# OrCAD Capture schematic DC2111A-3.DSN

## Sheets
1 SHEET1: size Custom; title: HIGH EFFICIENCY 4 PHASE 120A; rev: 3; company: TM
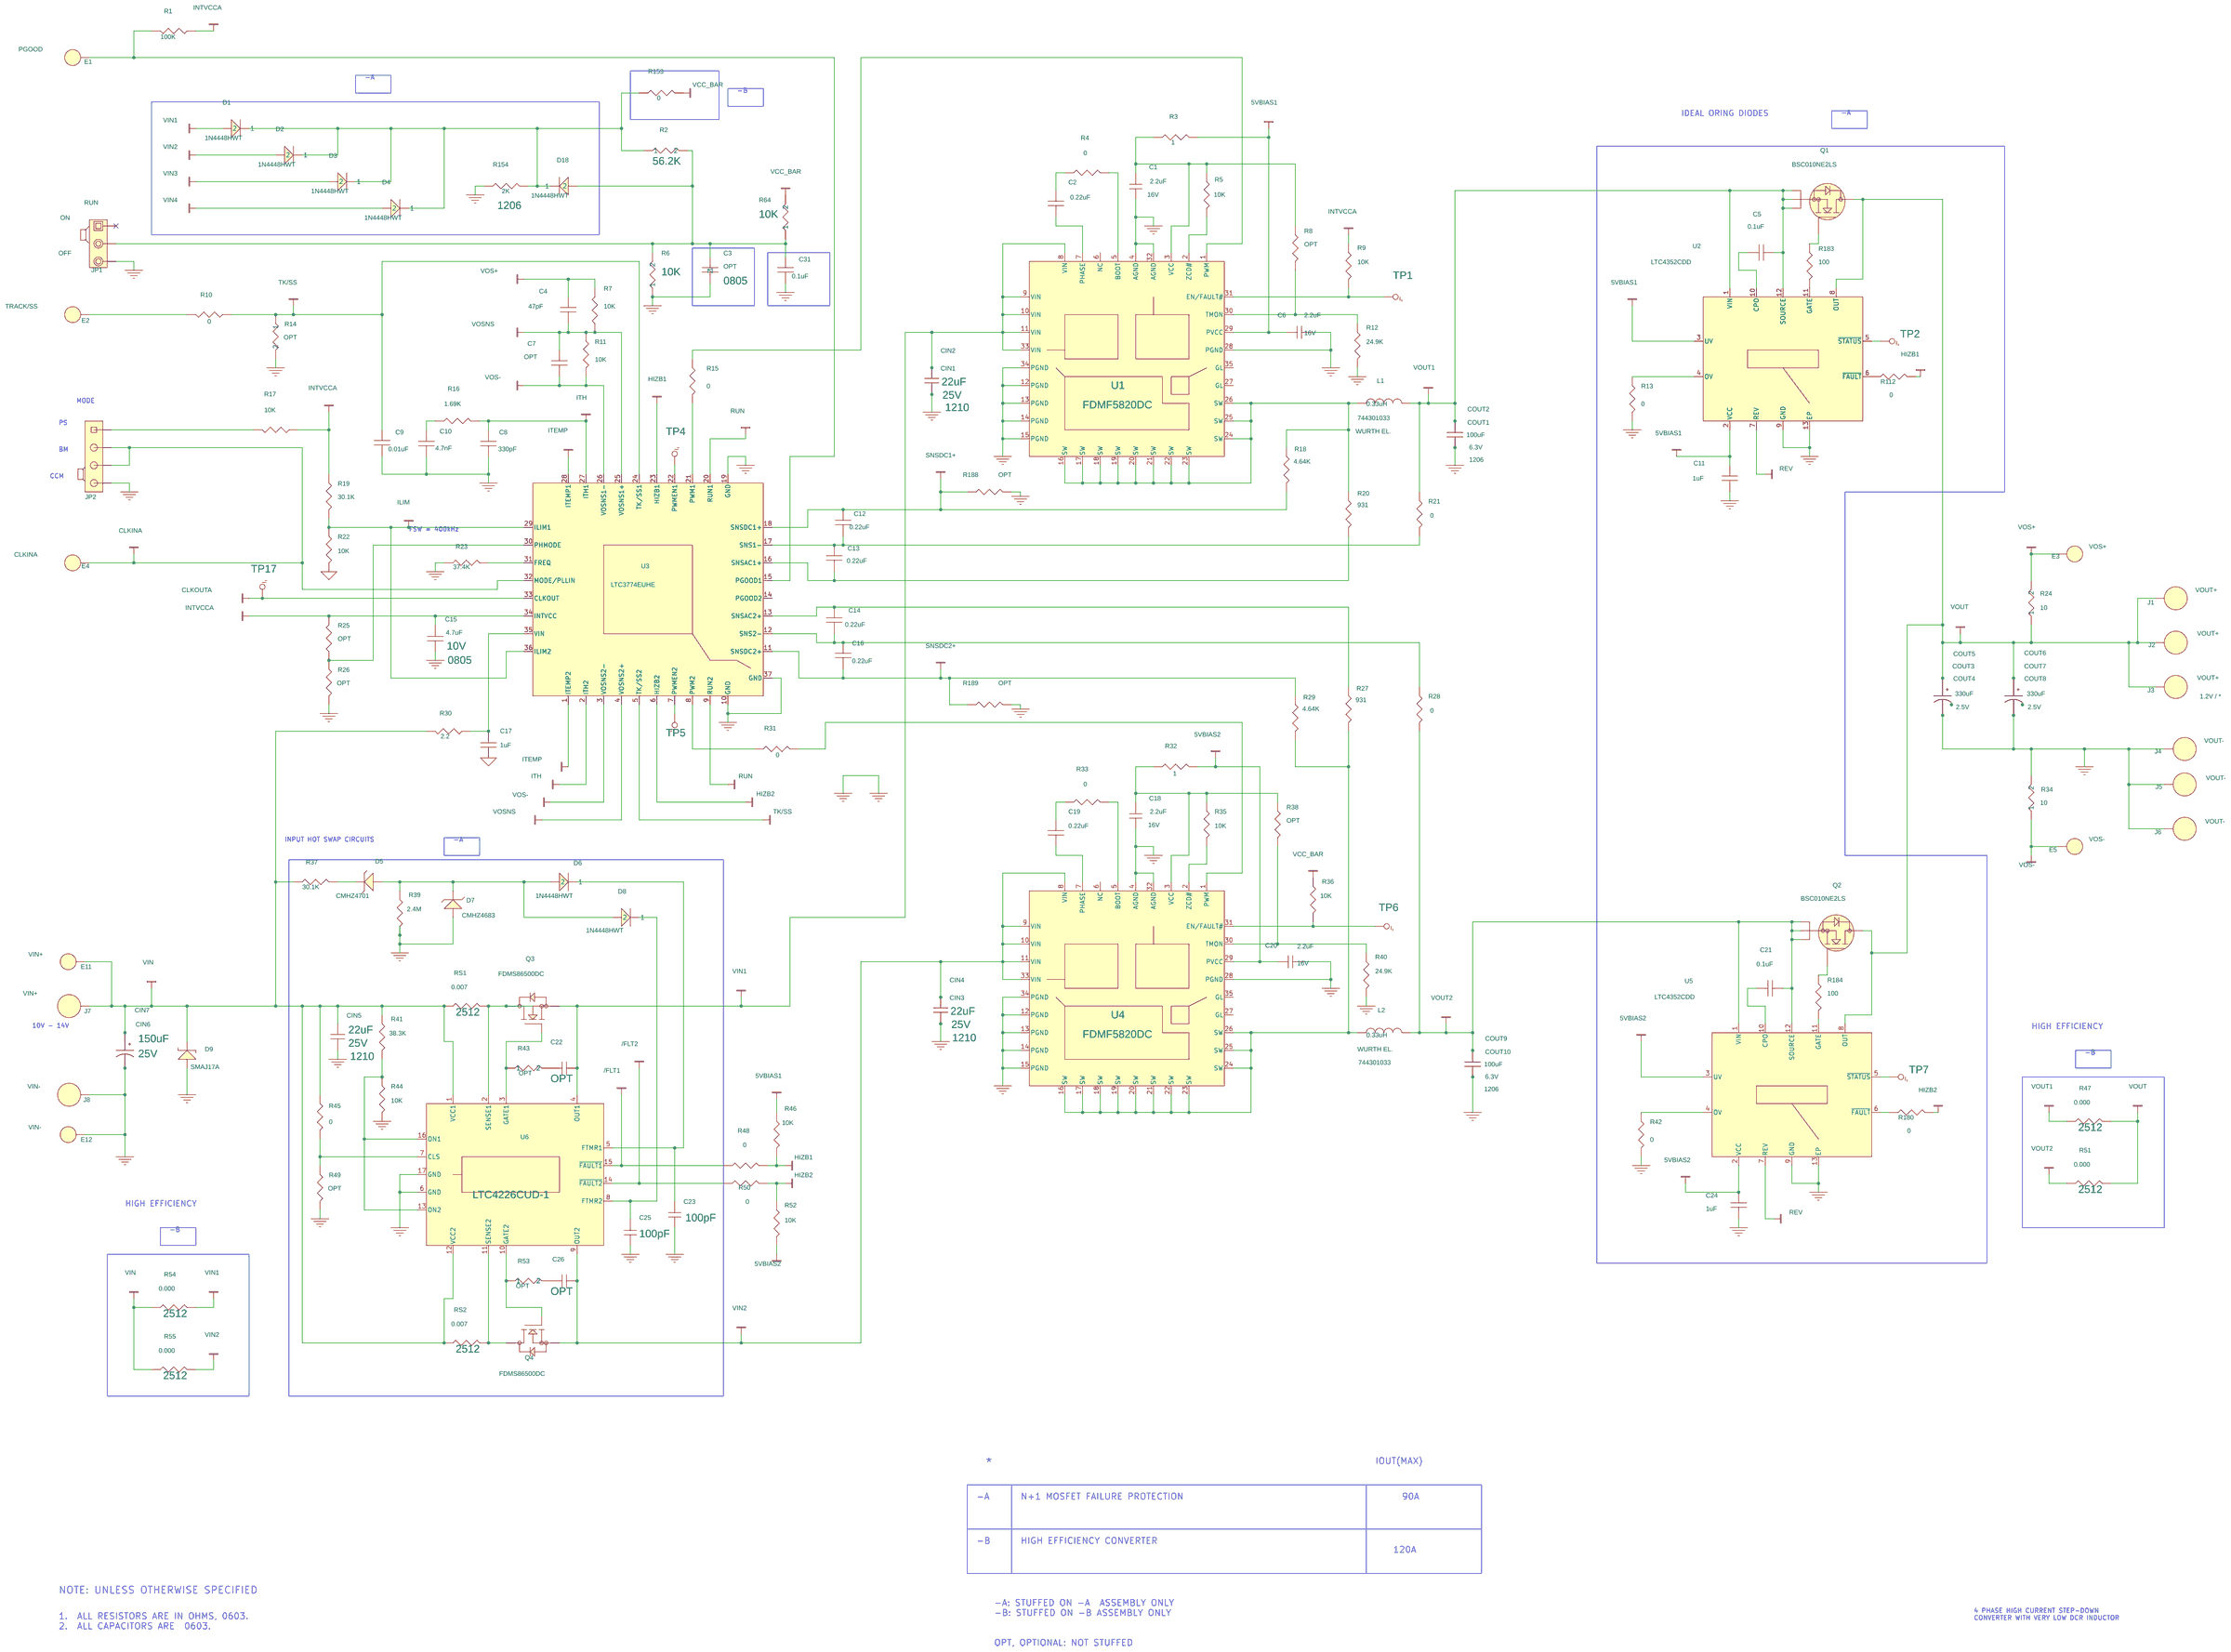
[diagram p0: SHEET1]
2 SHEET2: size Custom
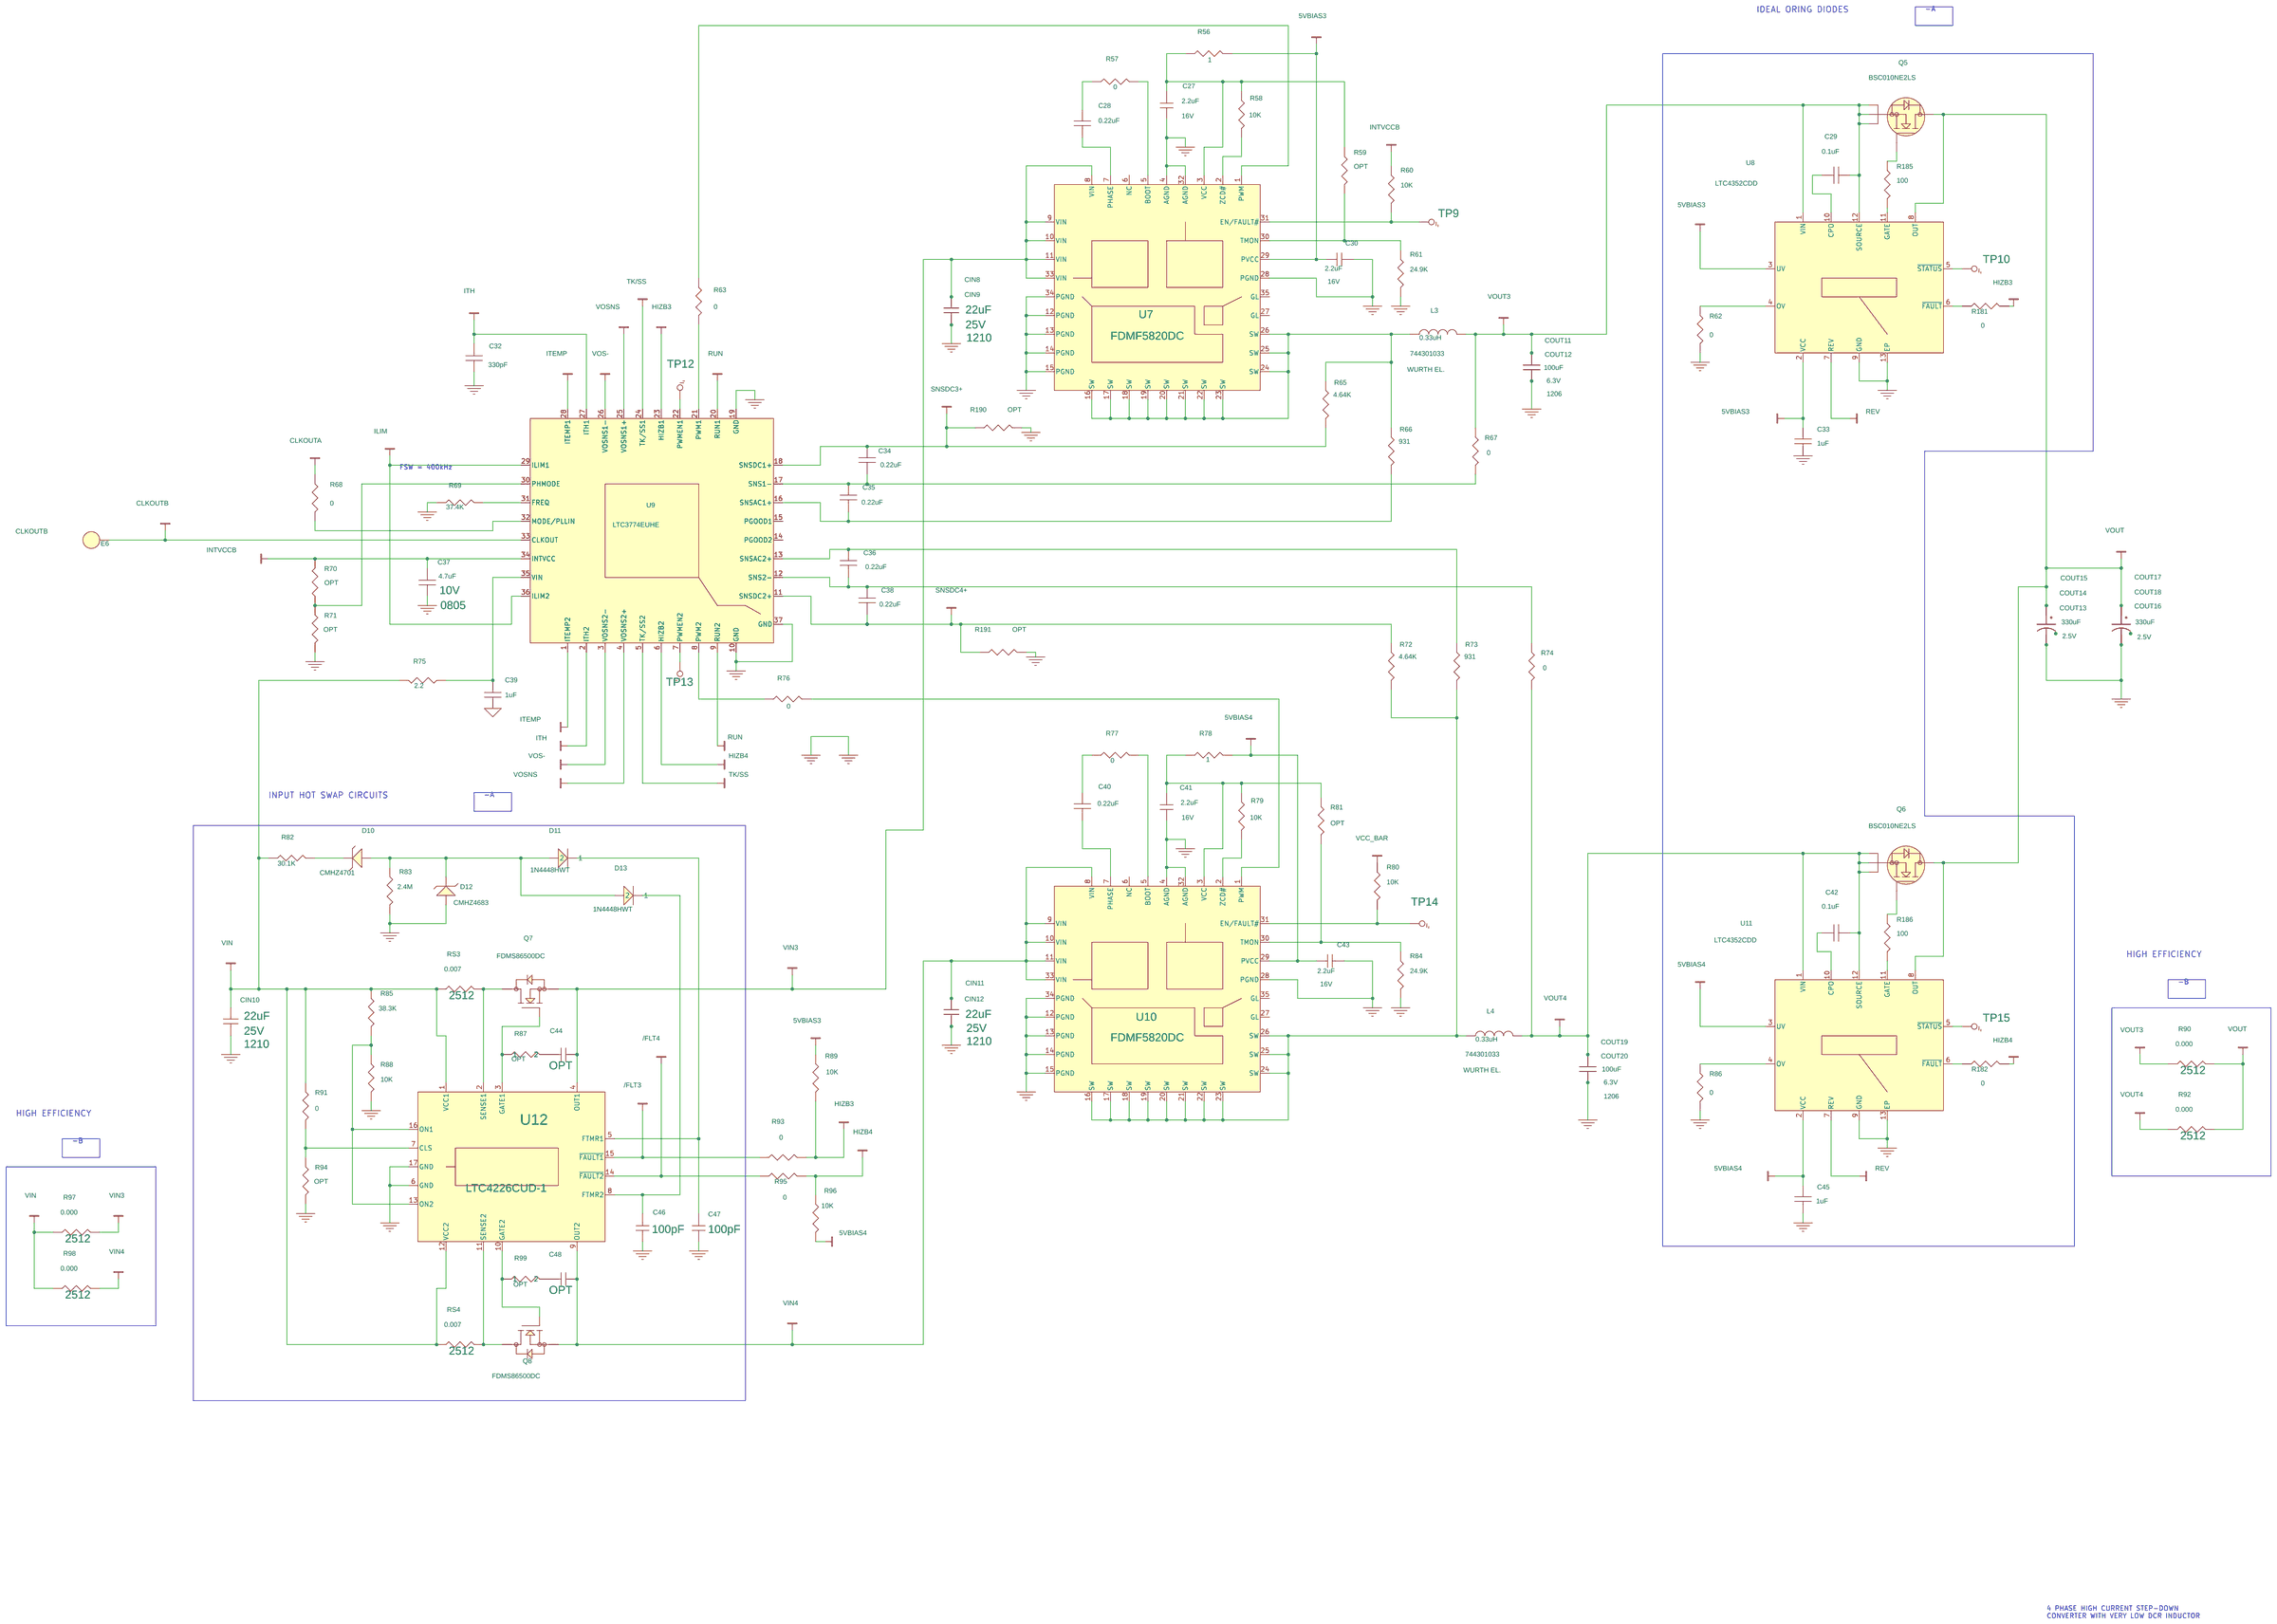
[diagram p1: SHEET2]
3 SHEET3: size Custom
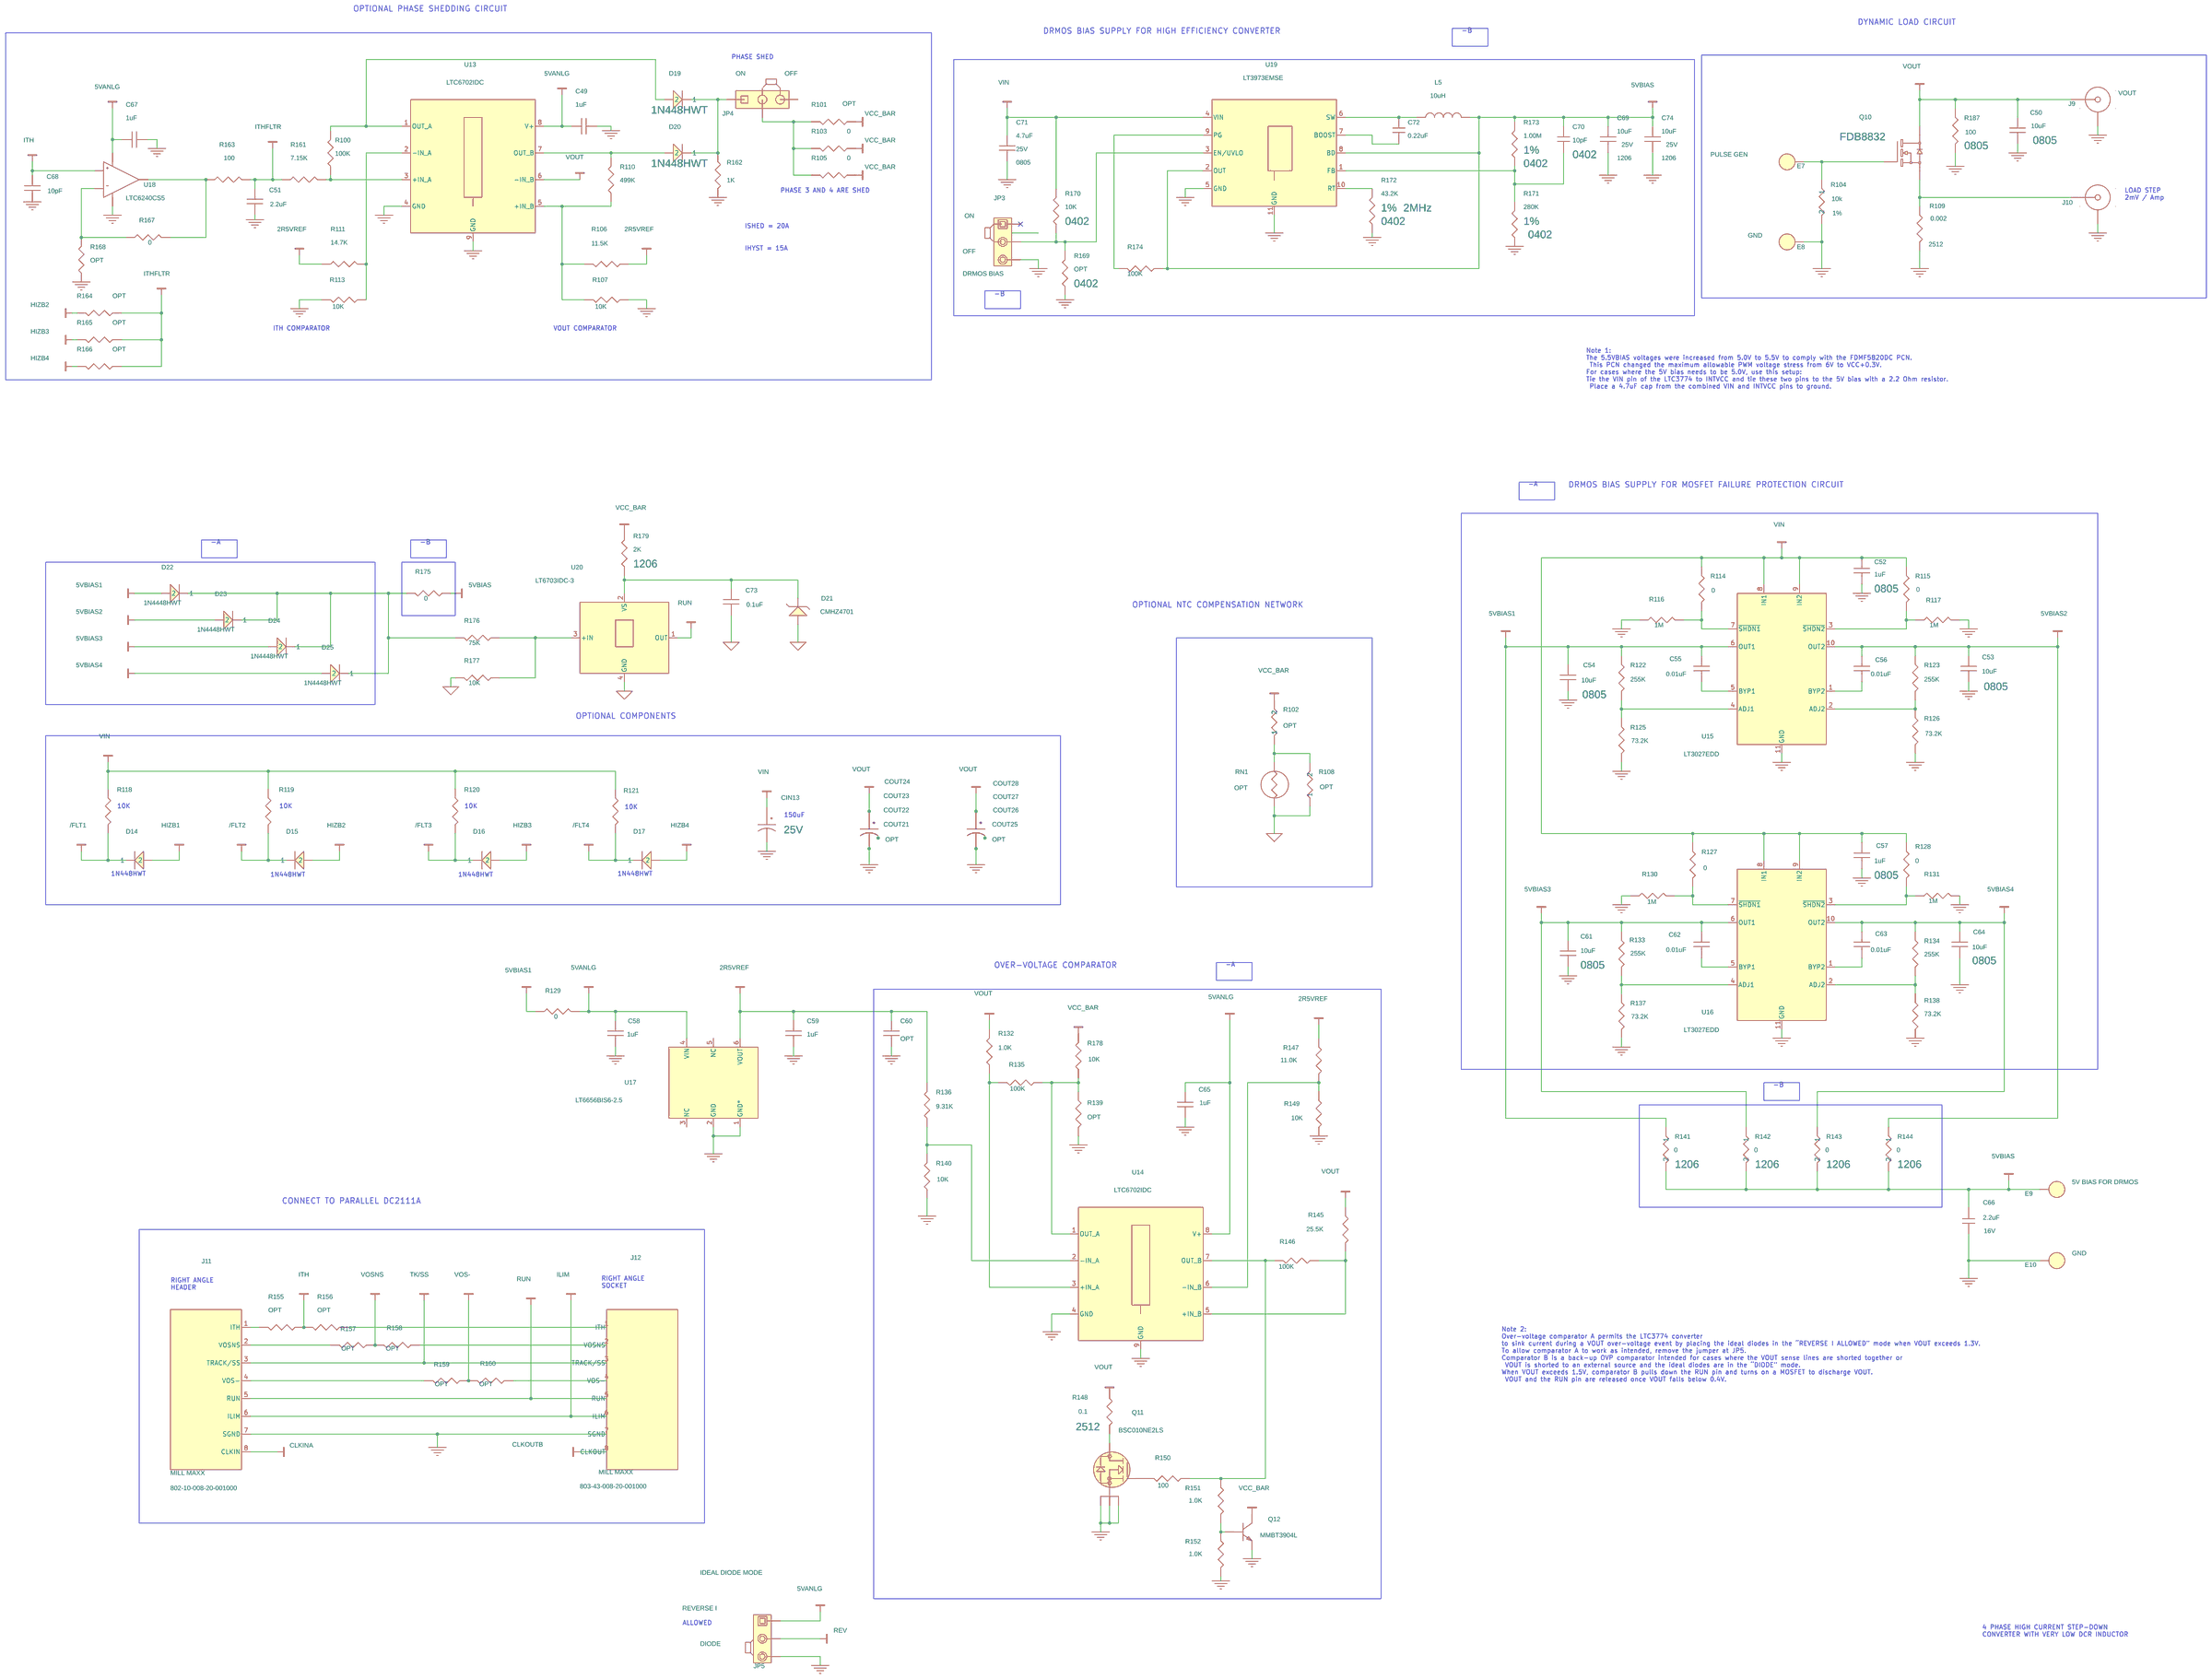
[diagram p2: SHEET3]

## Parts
sheet SHEET1
C1  2.2uF  [0603XS]
C2  0.22uF  [0603XS]
C3  OPT  [0805]
C4  47pF  [0603XS]
C5  0.1uF  [0603XS]
C6  2.2uF  [0603XS]
C7  OPT  [0603XS]
C8  330pF  [0603XS]
C9  0.01uF  [0603XS]
C10  4.7nF  [0603XS]
C11  1uF  [0603XS]
C12  0.22uF  [0603XS]
C13  0.22uF  [0603XS]
C14  0.22uF  [0603XS]
C15  4.7uF  [0805]
C16  0.22uF  [0603XS]
C17  1uF  [0603XS]
C18  2.2uF  [0603XS]
C19  0.22uF  [0603XS]
C20  2.2uF  [0603XS]
C21  0.1uF  [0603XS]
C22  OPT  [0603XS]
C23  100pF  [0603XS]
C24  1uF  [0603XS]
C25  100pF  [0603XS]
C26  OPT  [0603XS]
C31  0.1uF  [0603XS]
CIN1  22uF  [1210]
CIN2  22uF  [1210]
CIN3  22uF  [1210]
CIN4  22uF  [1210]
CIN5  22uF  [1210]
CIN6  150uF  [C-SANYO-HVH-8X10.5]
CIN7  150uF  [C-SANYO-HVH-8X10.5]
COUT1  100uF  [1206]
COUT2  100uF  [1206]
COUT3  330uF  [7343-D15T]
COUT4  330uF  [7343-D15T]
COUT5  330uF  [7343-D15T]
COUT6  330uF  [7343-D15T]
COUT7  330uF  [7343-D15T]
COUT8  330uF  [7343-D15T]
COUT9  100uF  [1206]
COUT10  100uF  [1206]
D1  1N4448HWT  [SOD523]
D2  1N4448HWT  [SOD523]
D3  1N4448HWT  [SOD523]
D4  1N4448HWT  [SOD523]
D5  CMHZ4701  [SOD123]
D6  1N4448HWT  [SOD523]
D7  CMHZ4683  [SOD123]
D8  1N4448HWT  [SOD523]
D9  SMAJ17A  [SMA-DIODE]
D18  1N4448HWT  [SOD523]
E1  Testpoint  [MM/2501]
E2  Testpoint  [MM/2501]
E3  Testpoint  [MM/2501]
E4  Testpoint  [MM/2501]
E5  Testpoint  [MM/2501]
E11  Testpoint  [MM/2501]
E12  Testpoint  [MM/2501]
J1  Testpin  [PAD450-190]
J2  Testpin  [PAD450-190]
J3  Testpin  [PAD450-190]
J4  Testpin  [PAD450-190]
J5  Testpin  [PAD450-190]
J6  Testpin  [PAD450-190]
J7  Testpin  [PAD450-190]
J8  Testpin  [PAD450-190]
JP1  3 Pins 2mm Ctrs.  [JP3X1/079]
JP2  4 Pins 2mm Ctrs.  [HDR_1X4_2MM]
L1  0.33uH  [I-FP1308R/5050/744301033]
L2  0.33uH  [I-FP1308R/5050/744301033]
Q1  BSC010NE2LS  [LFPAK]
Q2  BSC010NE2LS  [LFPAK]
Q3  FDMS86500DC  [POWER56]
Q4  FDMS86500DC  [POWER56]
R1  100K  [0603XS]
R2  56.2K  [0603XS]
R3  1  [0603XS]
R4  0  [0603XS]
R5  10K  [0603XS]
R6  10K  [0603XS]
R7  10K  [0603XS]
R8  OPT  [0603XS]
R9  10K  [0603XS]
R10  0  [0603XS]
R11  10K  [0603XS]
R12  24.9K  [0603XS]
R13  0  [0603XS]
R14  OPT  [0603XS]
R15  0  [0603XS]
R16  1.69K  [0603XS]
R17  10K  [0603XS]
R18  4.64K  [0603XS]
R19  30.1K  [0603XS]
R20  931  [0603XS]
R21  0  [0603XS]
R22  10K  [0603XS]
R23  37.4K  [0603XS]
R24  10  [0603XS]
R25  OPT  [0603XS]
R26  OPT  [0603XS]
R27  931  [0603XS]
R28  0  [0603XS]
R29  4.64K  [0603XS]
R30  2.2  [0603XS]
R31  0  [0603XS]
R32  1  [0603XS]
R33  0  [0603XS]
R34  10  [0603XS]
R35  10K  [0603XS]
R36  10K  [0603XS]
R37  30.1K  [0603XS]
R38  OPT  [0603XS]
R39  2.4M  [0603XS]
R40  24.9K  [0603XS]
R41  38.3K  [0603XS]
R42  0  [0603XS]
R43  OPT  [0603XS]
R44  10K  [0603XS]
R45  0  [0603XS]
R46  10K  [0603XS]
R47  0.000  [2512]
R48  0  [0603XS]
R49  OPT  [0603XS]
R50  0  [0603XS]
R51  0.000  [2512]
R52  10K  [0603XS]
R53  OPT  [0603XS]
R54  0.000  [2512]
R55  0.000  [2512]
R64  10K  [0603XS]
R112  0  [0603XS]
R153  0  [0603XS]
R154  2K  [1206]
R180  0  [0603XS]
R183  100  [0603XS]
R184  100  [0603XS]
R188  OPT  [0603XS]
R189  OPT  [0603XS]
RS1  0.007  [2512]
RS2  0.007  [2512]
TP1  PAD-30SQ  [PAD-30SQ]
TP2  PAD-30SQ  [PAD-30SQ]
TP4  PAD-30SQ  [PAD-30SQ]
TP5  PAD-30SQ  [PAD-30SQ]
TP6  PAD-30SQ  [PAD-30SQ]
TP7  PAD-30SQ  [PAD-30SQ]
TP17  PAD-30SQ  [PAD-30SQ]
U1  FDMF5820DC  [QFN-5X5-31]
U2  LTC4352CDD  [DFN12DD]
U3  LTC3774EUHE  [UHE-5X6-36P+1]
U4  FDMF5820DC  [QFN-5X5-31]
U5  LTC4352CDD  [DFN12DD]
U6  LTC4226CUD-1  [QFN16UD-3X3]
XJP1  2mm Ctrs.
XJP2  2mm Ctrs.
sheet SHEET2
C27  2.2uF  [0603XS]
C28  0.22uF  [0603XS]
C29  0.1uF  [0603XS]
C30  2.2uF  [0603XS]
C32  330pF  [0603XS]
C33  1uF  [0603XS]
C34  0.22uF  [0603XS]
C35  0.22uF  [0603XS]
C36  0.22uF  [0603XS]
C37  4.7uF  [0805]
C38  0.22uF  [0603XS]
C39  1uF  [0603XS]
C40  0.22uF  [0603XS]
C41  2.2uF  [0603XS]
C42  0.1uF  [0603XS]
C43  2.2uF  [0603XS]
C44  OPT  [0603XS]
C45  1uF  [0603XS]
C46  100pF  [0603XS]
C47  100pF  [0603XS]
C48  OPT  [0603XS]
CIN8  22uF  [1210]
CIN9  22uF  [1210]
CIN10  22uF  [1210]
CIN11  22uF  [1210]
CIN12  22uF  [1210]
COUT11  100uF  [1206]
COUT12  100uF  [1206]
COUT13  330uF  [7343-D15T]
COUT14  330uF  [7343-D15T]
COUT15  330uF  [7343-D15T]
COUT16  330uF  [7343-D15T]
COUT17  330uF  [7343-D15T]
COUT18  330uF  [7343-D15T]
COUT19  100uF  [1206]
COUT20  100uF  [1206]
D10  CMHZ4701  [SOD123]
D11  1N4448HWT  [SOD523]
D12  CMHZ4683  [SOD123]
D13  1N4448HWT  [SOD523]
E6  Testpoint  [MM/2501]
L3  0.33uH  [I-FP1308R/5050/744301033]
L4  0.33uH  [I-FP1308R/5050/744301033]
Q5  BSC010NE2LS  [LFPAK]
Q6  BSC010NE2LS  [LFPAK]
Q7  FDMS86500DC  [POWER56]
Q8  FDMS86500DC  [POWER56]
R56  1  [0603XS]
R57  0  [0603XS]
R58  10K  [0603XS]
R59  OPT  [0603XS]
R60  10K  [0603XS]
R61  24.9K  [0603XS]
R62  0  [0603XS]
R63  0  [0603XS]
R65  4.64K  [0603XS]
R66  931  [0603XS]
R67  0  [0603XS]
R68  0  [0603XS]
R69  37.4K  [0603XS]
R70  OPT  [0603XS]
R71  OPT  [0603XS]
R72  4.64K  [0603XS]
R73  931  [0603XS]
R74  0  [0603XS]
R75  2.2  [0603XS]
R76  0  [0603XS]
R77  0  [0603XS]
R78  1  [0603XS]
R79  10K  [0603XS]
R80  10K  [0603XS]
R81  OPT  [0603XS]
R82  30.1K  [0603XS]
R83  2.4M  [0603XS]
R84  24.9K  [0603XS]
R85  38.3K  [0603XS]
R86  0  [0603XS]
R87  OPT  [0603XS]
R88  10K  [0603XS]
R89  10K  [0603XS]
R90  0.000  [2512]
R91  0  [0603XS]
R92  0.000  [2512]
R93  0  [0603XS]
R94  OPT  [0603XS]
R95  0  [0603XS]
R96  10K  [0603XS]
R97  0.000  [2512]
R98  0.000  [2512]
R99  OPT  [0603XS]
R181  0  [0603XS]
R182  0  [0603XS]
R185  100  [0603XS]
R186  100  [0603XS]
R190  OPT  [0603XS]
R191  OPT  [0603XS]
RS3  0.007  [2512]
RS4  0.007  [2512]
TP9  PAD-30SQ  [PAD-30SQ]
TP10  PAD-30SQ  [PAD-30SQ]
TP12  PAD-30SQ  [PAD-30SQ]
TP13  PAD-30SQ  [PAD-30SQ]
TP14  PAD-30SQ  [PAD-30SQ]
TP15  PAD-30SQ  [PAD-30SQ]
U7  FDMF5820DC  [QFN-5X5-31]
U8  LTC4352CDD  [DFN12DD]
U9  LTC3774EUHE  [UHE-5X6-36P+1]
U10  FDMF5820DC  [QFN-5X5-31]
U11  LTC4352CDD  [DFN12DD]
U12  LTC4226CUD-1  [QFN16UD-3X3]
sheet SHEET3
C49  1uF  [0603XS]
C50  10uF  [0805]
C51  2.2uF  [0603XS]
C52  1uF  [0805]
C53  10uF  [0805]
C54  10uF  [0805]
C55  0.01uF  [0603XS]
C56  0.01uF  [0603XS]
C57  1uF  [0805]
C58  1uF  [0603XS]
C59  1uF  [0603XS]
C60  OPT  [0603XS]
C61  10uF  [0805]
C62  0.01uF  [0603XS]
C63  0.01uF  [0603XS]
C64  10uF  [0805]
C65  1uF  [0603XS]
C66  2.2uF  [0603XS]
C67  1uF  [0603XS]
C68  10pF  [0603XS]
C69  10uF  [1206]
C70  10pF  [0402]
C71  4.7uF  [0805]
C72  0.22uF  [0603]
C73  0.1uF  [0603XS]
C74  10uF  [1206]
CIN13  OPT  [C-SANYO-HVH-8X10.5]
COUT21  OPT  [7343-D15T]
COUT22  OPT  [7343-D15T]
COUT23  OPT  [7343-D15T]
COUT24  OPT  [7343-D15T]
COUT25  OPT  [7343-D15T]
COUT26  OPT  [7343-D15T]
COUT27  OPT  [7343-D15T]
COUT28  OPT  [7343-D15T]
D14  OPT  [SOD523]
D15  OPT  [SOD523]
D16  OPT  [SOD523]
D17  OPT  [SOD523]
D19  1N448HWT  [SOD523]
D20  1N448HWT  [SOD523]
D21  CMHZ4701  [SOD123]
D22  1N4448HWT  [SOD523]
D23  1N4448HWT  [SOD523]
D24  1N4448HWT  [SOD523]
D25  1N4448HWT  [SOD523]
E7  Testpoint  [MM/2501]
E8  Testpoint  [MM/2501]
E9  Testpoint  [MM/2501]
E10  Testpoint  [MM/2501]
J9  Connector  [BNC5]
J10  Connector  [BNC5]
J11  802-10-008-20-001000  [HEADER-2X4-100-R]
J12  803-43-008-20-001000  [SOCKET-2X4-100-R]
JP3  3 Pins 2mm Ctrs.  [JP3X1/079]
JP4  3 Pins 2mm Ctrs.  [JP3X1/079]
JP5  3 Pins 2mm Ctrs.  [JP3X1/079]
L5  10uH  [XAL4040]
Q10  FDB8832  [TO263AB]
Q11  BSC010NE2LS  [LFPAK]
Q12  MMBT3904L  [SOT23]
R100  100K  [0603XS]
R101  OPT  [0603XS]
R102  OPT  [0603XS]
R103  0  [0603XS]
R104  10k  [0603XS]
R105  0  [0603XS]
R106  11.5K  [0603XS]
R107  10K  [0603XS]
R108  OPT  [0603XS]
R109  0.002  [2512]
R110  499K  [0603XS]
R111  14.7K  [0603XS]
R113  10K  [0603XS]
R114  0  [0603XS]
R115  0  [0603XS]
R116  1M  [0603XS]
R117  1M  [0603XS]
R118  OPT  [0603XS]
R119  OPT  [0603XS]
R120  OPT  [0603XS]
R121  OPT  [0603XS]
R122  255K  [0603XS]
R123  255K  [0603XS]
R125  73.2K  [0603XS]
R126  73.2K  [0603XS]
R127  0  [0603XS]
R128  0  [0603XS]
R129  0  [0603XS]
R130  1M  [0603XS]
R131  1M  [0603XS]
R132  1.0K  [0603XS]
R133  255K  [0603XS]
R134  255K  [0603XS]
R135  100K  [0603XS]
R136  9.31K  [0603XS]
R137  73.2K  [0603XS]
R138  73.2K  [0603XS]
R139  OPT  [0603XS]
R140  10K  [0603XS]
R141  0  [1206]
R142  0  [1206]
R143  0  [1206]
R144  0  [1206]
R145  25.5K  [0603XS]
R146  100K  [0603XS]
R147  11.0K  [0603XS]
R148  0.1  [2512]
R149  10K  [0603XS]
R150  100  [0603XS]
R151  1.0K  [0603XS]
R152  1.0K  [0603XS]
R155  OPT  [0603XS]
R156  OPT  [0603XS]
R157  OPT  [0603XS]
R158  OPT  [0603XS]
R159  OPT  [0603XS]
R160  OPT  [0603XS]
R161  7.15K  [0603XS]
R162  1K  [0603XS]
R163  100  [0603XS]
R164  OPT  [0603XS]
R165  OPT  [0603XS]
R166  OPT  [0603XS]
R167  0  [0603XS]
R168  OPT  [0603XS]
R169  OPT  [0402]
R170  10K  [0402]
R171  280K  [0402]
R172  43.2K  [0402]
R173  1.00M  [0402]
R174  100K  [0603]
R175  0  [0603XS]
R176  75K  [0603XS]
R177  10K  [0603XS]
R178  10K  [0603XS]
R179  2K  [1206]
R187  100  [0805]
RN1  OPT  [0603\0805]
U13  LTC6702IDC  [DFN8DC]
U14  LTC6702IDC  [DFN8DC]
U15  LT3027EDD  [DFN10DD]
U16  LT3027EDD  [DFN10DD]
U17  LT6656BIS6-2.5  [SOT6]
U18  LTC6240CS5  [SOT23-5]
U19  LT3973EMSE  [MSOP-10PIN]
U20  LT6703IDC-3  [DFN3DC]
XJP3  2mm Ctrs.
XJP4  2mm Ctrs.
XJP5  2mm Ctrs.

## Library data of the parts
C1 C6 C18 C20 C27 C30 C41 C43 C66 = CAP-NP: CAP, 0603 2.2uF 10% 16V X5R; Grade: X5R; Part Number: C0603C225K4PAC; Voltage rating: 16V
C2 C19 C28 C40 = EMK107BJ224MA: CAP, 0603 0.22uF 10% 25V X5R
C3 = CAP_NP_1: CAP, 0603 0.1uF 10% 50V X7R; Part Number: TDK C1608X7R1H104K; Voltage: 50V
C4 C7 C9 C31 = EMK107BJ224MA: CAP, X5R, 0.01uF, 25V,10%, 0603; 4th Part Field: AVX; 5th Part Field: 06033C103KAT2A; Part Number: TDK C1608X7R1E224K
C5 C11 C21 C24 C29 C33 C42 C45 = EMK107BJ224MA: CAP, 0603 0.1uF 10% 16V X5R; 4th Part Field: AVX; 5th Part Field: 0603YD104KAT2A
C8 C32 = 06033A101JAT2A: CAP, 0603 100pF 5% 25V NPO; Part Number: AVX 06033A101JAT2A
C10 = 06033A471KAT2A: CAP, 0603 680pF 10% 25V X7R; Part Number: AVX 06033C681KAT2A
C12-C14 C16 C34-C36 C38 = EMK107BJ224MA: CAP, 0603 0.22uF 10% 25V X7R; Part Number: TDK C1608X7R1E224K
C15 C37 = CAP_NP_3: CAP, 0805 4.7uF 10% 10V X5R; Part Number: TAIYO YUDEN LMK212BJ475KG-T; Voltage: 10V
C17 C39 C50 = TMK107BJ105MA: CAP, 0603 1uF 20% 25V X5R; Part Number: AVX 06033D105MAT2A
C22 C26 C44 C48 = CAP-NP: CAP, 0603 0.01uF 10% 50V X7R; Part Number: AVX 0603ZC104KAT; VOLTAGE: X5R
C23 C25 C46 C47 = CAP-NP: CAP, 0603 0.1uF 10% 10V X7R; Part Number: AVX 0603ZC104KAT; VOLTAGE: X5R
CIN1 CIN12 = C3225X5R0J476M_1: CAP, 1210 22uF 20% 16V X5R; 1st Part Field: 25V; 4th Part Field: Taiyo Yuden; 5th Part Field: TDK C3225X5R1C226MT; Part Number: AVX 1210YD226MAT2A
CIN2 CIN9 = C3225X5R0J476M_2: CAP, 1210 22uF 20% 16V X5R; 1st Part Field: 25V; 4th Part Field: Taiyo Yuden; 5th Part Field: TDK C3225X5R1C226MT; Part Number: AVX 1210YD226MAT2A
CIN3 CIN10 = C3225X5R0J476M: CAP, 1210 22uF 20% 16V X5R; 1st Part Field: 25V; 4th Part Field: Taiyo Yuden; 5th Part Field: TDK C3225X5R1C226MT; Part Number: AVX 1210YD226MAT2A
CIN4 CIN11 = C3225X5R0J476M_4: CAP, 1210 22uF 20% 16V X5R; 1st Part Field: 25V; 4th Part Field: Taiyo Yuden; 5th Part Field: TDK C3225X5R1C226MT; Part Number: AVX 1210YD226MAT2A
CIN5 CIN8 = C3225X5R0J476M_3: CAP, 1210 22uF 20% 16V X5R; 1st Part Field: 25V; 4th Part Field: Taiyo Yuden; 5th Part Field: TDK C3225X5R1C226MT; Part Number: AVX 1210YD226MAT2A
CIN6 CIN13 = 16SEPC470M: CAP, 150uF 20% 25V Alum-poly; 1st Part Field: 25V; 3rd Part Field: Alum-polymer; 4th Part Field: SunCon; 5th Part Field: HVH150MS; Part Number: SANYO 16SVP180MX
CIN7 = 16SEPC470M_1: CAP, 150uF 20% 25V Alum-poly; 1st Part Field: 25V; 3rd Part Field: Alum-polymer; 4th Part Field: SunCon; 5th Part Field: HVH150MS; Part Number: SANYO 16SVP180MX
COUT1 COUT2 COUT9-COUT12 COUT19 COUT20 = CAP_NP_4: CAP, 1206 100uF 20% 6.3V X5R; Part Number: TAIYO YUDEN JMK316BJ107ML-T; Voltage: 6.3V
COUT3-COUT8 COUT13-COUT18 COUT21-COUT28 = tant_2: CAP, 7343 330uF 20% 2.5V POSCAP; Part Number: SANYO 2R5TPE330M9; Voltage: 2.5V
D1 D11 D23 = DIODE_0_1
D2 D14 = DIODE_0_2
D3 D15 = DIODE_0_6
D4 D25 = DIODE_0_5
D5 D7 D10 D12 D21 = DIODE-SUPPRESSOR
D6 D13 D16 = DIODE_0
D8 D22 = DIODE_0_3
D9 = DIODE-ZENER
D18 D19 = DIODE_0_4
E1 = MillMax-2501_0: TURRET; 9th Part Field: PGOOD; Part Number: MILL MAX 2501-2-00-80-00-00-07-0
E2 = MillMax-2501_0: TURRET; 9th Part Field: TRACK/SS; Part Number: MILL MAX 2501-2-00-80-00-00-07-0
E3 = MillMax-2501_0: TURRET; 10th Part Field: 1.2V / 25A; 9th Part Field: VOS+; Part Number: MILL MAX 2501-2-00-80-00-00-07-0
E4 = MillMax-2501_0: TURRET; 9th Part Field: CLKINA; Part Number: MILL MAX 2501-2-00-80-00-00-07-0
E5 = MillMax-2501_0: TURRET; 10th Part Field: 1.2V / 25A; 9th Part Field: VOS-; Part Number: MILL MAX 2501-2-00-80-00-00-07-0
E11 = MillMax-2501_0: TURRET; 10th Part Field: 1.2V / 25A; 9th Part Field: VIN+; Part Number: MILL MAX 2501-2-00-80-00-00-07-0
E12 = MillMax-2501_0: TURRET; 10th Part Field: 1.2V / 25A; 9th Part Field: VIN-; Part Number: MILL MAX 2501-2-00-80-00-00-07-0
J1 J2 = STUD_0: STUD, TEST PIN; 10th Part Field: 1.2V / *; 9th Part Field: VOUT+; Part Number: PEM KFH-032-10
J3 = STUD_0: STUD, TEST PIN; 10th Part Field: 1.2V / 180A; 9th Part Field: VOUT+; Part Number: PEM KFH-032-10
J4-J6 = STUD_0: STUD, TEST PIN; 10th Part Field: 4.5V - 14V; 9th Part Field: VOUT-; Part Number: PEM KFH-032-10
J7 = STUD_0: STUD, TEST PIN; 10th Part Field: 1.2V / 180A; 9th Part Field: VIN+; Part Number: PEM KFH-032-10
J8 = STUD_0: STUD, TEST PIN; 10th Part Field: 1.2V / 180A; 9th Part Field: VIN-; Part Number: PEM KFH-032-10
JP1 = Samtec_TMM-103-02-L-S: HEADER, 3 PIN; 11th Part Field: OFF; 12th Part Field: RUN; 9th Part Field: ON; Part Number: SAMTEC TMM-103-02-L-S
JP2 = Commcon2802s03g2_0: 11th Part Field: OFF; 12th Part Field: RUN; 9th Part Field: ON
L1-L4 = 744355147_Wurth: 4th Part Field: WURTH EL.; 5th Part Field: 744301033
Q1 Q2 Q5 Q6 Q11 = MOSFET_N-DIODE-A-LFPAK_0
Q3 Q4 Q7 Q8 = MOSFET-Si7164DP-SO8-POWERPAK_0
R1 = CR16-2002FM_4: RES, 0603 20K OHMS 1% 1/10W; Part Number: NIC NRC06F2002TRF
R2 R143 = CR16-104JM_2: Part Number: VISHAY CRCW060330K1FKEA
R3 R5 R8 R9 R12 R13 R32 R35 R36 R38-R42 R44 R46 R47 R51 R52 R54-R56 R58-R62 R78-R81 R83-R86 R88-R90 R92 R96-R98 R100 R111 R112 R118-R121 R139 R161 R163 R167 R169 R170 R174 R180-R186 RS1-RS4 = CJ06-000M: RES, 0603 1 OHM 5% 1/10W; Part Number: VISHAY CRCW06031R00JNEA
R4 R21 R28 R30 R33 R57 R67 R74 R75 R77 = CJ06-000M: RES, 0603 0 OHM JUMPER; Part Number: YAGEO RC0603FR-070RL
R6 R142 = CR16-104JM_1: Part Number: VISHAY CRCW060330K1FKEA
R7 = CR16-2002FM_7: RES, 0603 15.0k OHMS 1% 1/10W; 5th Part Field: CR16-1502FM; Part Number: VISHAY CRCW060330K1FKEA
R10 R15 R31 R37 R45 R48 R50 R63 R68 R76 R82 R91 R93 R95 R103 R105 R114 R115 R127 R128 R153 R187 = RES0603: RES, 0603 0 Ohm jumper; 6th Part Field: OPT; Part Number: OPTION
R11 = CR16-2002FM_8: RES, 0603 10.0k OHMS 1% 1/10W; 5th Part Field: CR16-1002FM; Part Number: VISHAY CRCW060330K1FKEA
R14 R141 = CR16-104JM: Part Number: VISHAY CRCW060330K1FKEA
R16 = CR16-2002FM_1: RES, 0603 20K OHMS 1% 1/10W; Part Number: NIC NRC06F2002TRF
R17 = CR16-2002FM_6: RES, 0603 10.0k OHMS 1% 1/10W; 5th Part Field: CR16-1002FM; Part Number: VISHAY CRCW060330K1FKEA
R18 R20 R27 R29 R65 R66 R72 R73 = CRCW06032K87FKEA
R19 = CR16-2002FM: RES, 0603 3.01K OHMS 1% 1/10W; 5th Part Field: CR16-3011FM; Part Number: VISHAY CRCW060330K1FKEA
R22 = CR16-2002FM_5: RES, 0603 1.0K OHMS 1% 1/10W; 5th Part Field: CR16-1002FM; Part Number: VISHAY CRCW060330K1FKEA
R23 = CR16-2002FM_2: RES, 0603 100k OHMS 1% 1/10W; 5th Part Field: CR16-1003FM; Part Number: VISHAY CRCW060330K1FKEA
R24 R99 = CR16-510JM: RES, 0603 51 OHMS 5% 1/10W; Part Number: VISHAY CRCW060351R0JNEA
R25 R26 R49 R70 R71 R94 R188-R191 = RES0603: RES, 0603 OPTION; Part Number: OPTION
R34 R87 = CR16-510JM_1: RES, 0603 51 OHMS 5% 1/10W; Part Number: VISHAY CRCW060351R0JNEA
R43 = CR16-510JM_3: RES, 0603 51 OHMS 5% 1/10W; Part Number: VISHAY CRCW060351R0JNEA
R53 = CR16-510JM_2: RES, 0603 51 OHMS 5% 1/10W; Part Number: VISHAY CRCW060351R0JNEA
R64 R144 = CR16-104JM_3: Part Number: VISHAY CRCW060330K1FKEA
R154 = CR16-2002FM_3: RES, 0603 20K OHMS 1% 1/10W; Part Number: NIC NRC06F2002TRF
TP1 TP2 TP4-TP7 TP9 TP10 TP12-TP15 TP17 = PAD-30SQ
U1 U4 U7 U10 = R2J20602NP(Renesas)_12
U2 U5 U8 U11 = LTC4352CDD-DFN12DD
U3 U9 = LTC1629_13: IC, DUAL OUTPUT BUCK CONTROLLER; Part Number: LINEAR TECH. LTC3860EUH
U6 U12 = LTC4226CUD-QFN16UD_5
XJP1-XJP3 XJP5 = Samtec_2SN-BK-G: SHUNT; Part Number: SAMTEC 2SN-BK-G
E6 = MillMax-2501_0: TURRET; 9th Part Field: CLKOUTB; Part Number: MILL MAX 2501-2-00-80-00-00-07-0
R69 = CR16-2002FM: RES, 0603 100k OHMS 1% 1/10W; 5th Part Field: CR16-1003FM; Part Number: VISHAY CRCW060330K1FKEA
C49 C51 C52 C57-C60 C65 C67 C68 C73 = CAP_NP: CAP, 0805 1uF 20% 25V X5R; FIELD1: 1206; Part Number: TDK C2012X7R1E105M; Tolerance: X7R
C53 C54 C61 C64 = CAP_NP: CAP, 0805 10uF 20% 6.3V X5R; Part Number: TAIYO YUDEN, JMK212BJ106MG-T; Tolerance: X5R
C55 C56 C62 C63 = CAP_NP: CAP, 0402 0.01uF 10% 25V X7R; FIELD1: 0402; Part Number: AVX 04023C103KAT; Tolerance: X7R
C69 C71 C74 = UMK325BJ105MH: 1st Part Field: 25V
C70 C72 = CAP-NP
D17 = DIODE_0_7
D20 = DIODE_0_9
D24 = DIODE_0_8
E7 = MillMax-2501_0: TURRET; 9th Part Field: PULSE GEN; Part Number: MILL MAX 2501-2-00-80-00-00-07-0
E8 E10 = MillMax-2501_0: TURRET; 9th Part Field: GND; Part Number: MILL MAX 2501-2-00-80-00-00-07-0
E9 = MillMax-2501_0: TURRET; 9th Part Field: 5V BIAS FOR DRMOS; Part Number: MILL MAX 2501-2-00-80-00-00-07-0
J9 = Connex_112404_gnd2_0: CON, BNC, 5 PINS; 10th Part Field: 5% DUTY CYCLE MAX.; 11th Part Field: 10mV / A; 7th Part Field: BNC; 9th Part Field: VOUT; Part Number: CONNEX 112404
J10 = Connex_112404_gnd2_0_1: CON, BNC, 5 PINS; 10th Part Field: 5% DUTY CYCLE MAX.; 11th Part Field: 10mV / A; 7th Part Field: BNC; 9th Part Field: VOUT; Part Number: CONNEX 112404
J11 = HD2X6-079-PMBUS_11: Label: PMBUS; Manufacturer: MILL MAXX; Manufacturer P/N: 802-40-008-20-001000; Part Type: Header; Type: header 12POS 2MM VERT; Vendor: Digikey; Vendor P/N: WM18561-ND
J12 = HD2X6-079-PMBUS_12: Label: PMBUS; Manufacturer: MILL MAXX; Part Type: Header; Type: header 12POS 2MM VERT; Vendor: Digikey; Vendor P/N: WM18561-ND
JP3 = Samtec_TMM-103-02-L-S: HEADER, 3 PIN; 11th Part Field: OFF; 12th Part Field: DRMOS BIAS; 9th Part Field: ON; Part Number: SAMTEC TMM-103-02-L-S
JP4 = Commcon2802s03g2_1: 11th Part Field: OFF; 12th Part Field: ON; 9th Part Field: ON
JP5 = Samtec_TMM-103-02-L-S: HEADER, 3 PIN; 11th Part Field: DIODE; 12th Part Field: IDEAL DIODE MODE; 9th Part Field: REVERSE I; Part Number: SAMTEC TMM-103-02-L-S
L5 = IND: 5th Part Field: MPI4040R3-220-R
Q10 = Si7806BDN_1: XSTR, MOSFET; Part Number: VISHAY SILICONIX SUD50N03-12P
Q12 = MMBT3904L_0
R101 R164-R166 = RES0603: RES, 0603 0 Ohm jumper; Part Number: OPTION
R102 = R_1: RES, 0603 OPTION; Part Number: OPTION
R104 = CR16-103JM: RES, 0603 10K OHMS 1% 1/10W; 2nd Part Field: 1%; Part Number: NIC NRC06F1002TRF
R106 R107 R110 R113 R129 R132 R135 R136 R140 R145-R152 R155-R160 R162 R168 R175-R179 = LR2512-01-R020-F
R108 = R: RES, 0603 OPTION; Part Number: OPTION
R109 = LR2010-01-R020-F: RES. 2010 0.010 OHMS 2% 1W; 5th Part Field: LR2010-01-R010-F; Part Number: IRC LRC-LRF2010LF-01-R010-F
R116 R117 R122 R123 R130 R131 R133 R134 = RESISTOR: RES, 0402 255K OHM 1% 1/16W; FIELD1: 0402; Part Number: ACC CR05-2553FM; Tolerance: 1%
R125 R126 R137 R138 = RESISTOR: RES, 0402 82.5K OHM 1% 1/16W; FIELD1: 0402; Part Number: ACC CR05-8252FM; Tolerance: 1%
R171-R173 = CJ06-000M: RES, 0603 1 OHM 5% 1/10W; 1st Part Field: 1%; 2nd Part Field: 2MHz; Part Number: VISHAY CRCW06031R00JNEA
RN1 = RNTC: THERMISTOR, 0805 100K OHMS 5% / 0603 4250 OHMS 2%; Part Number: MURATA NCP18WF104J03RB /
U13 U14 = LTC6702IDC
U15 U16 = LT3023EDD-10DFN_0: IC, LT3027EDD; Part Number: LINEAR TECH. LT3027EDD
U17 = BOX3_1
U18 = LTC2054CS5-SOT23-5-AMP_0
U19 = LT3973EMSE-MSE10_0
U20 = LT6703IDC-3_2
XJP4 = CommconCCIJ2MM-138G

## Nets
5VANLG: C49.1 C58.1 C65.1 C67.1 JP5.1 R129.2 U13.8(V+) U14.8(V+) U17.4(VIN) U18.5
5VBIAS: C66.2 C69.1 C70.1 C74.1 E9.1 L5.2 R141.2 R142.2 R143.2 R144.2 R173.1 R174.2 R175.2 U19.2(OUT) U19.8(BD)
5VBIAS1: C6.1 C11.1 C54.1 C55.1 D22.2 R3.2 R46.1 R122.1 R129.1 R141.1 U1.29(PVCC) U2.2(VCC) U2.3(UV) U15.6(OUT1)
5VBIAS2: C20.1 C24.1 C53.1 C56.1 D23.2 R32.2 R52.2 R123.1 R144.1 U4.29(PVCC) U5.2(VCC) U5.3(UV) U15.10(OUT2)
5VBIAS3: C30.1 C33.1 C61.1 C62.1 D24.2 R56.2 R89.1 R133.1 R142.1 U7.29(PVCC) U8.2(VCC) U8.3(UV) U16.6(OUT1)
5VBIAS4: C43.1 C45.1 C63.1 C64.1 D25.2 R78.2 R96.2 R134.1 R143.1 U10.29(PVCC) U11.2(VCC) U11.3(UV) U16.10(OUT2)
AGND: C1.1 C3.2 C6.2 C8.1 C9.2 C10.1 C11.2 C15.2 C17.1 C18.1 C20.2 C23.1 C24.2 C25.1 C27.1 C30.2 C31.2 C32.1 C33.2 C37.2 C39.1 C41.1 C43.2 C45.2 C46.1 C47.1 C49.2 C50.2 C51.2 C52.2 C53.2 C54.2 C57.2 C58.2 C59.2 C60.2 C61.2 C64.2 C65.2 C66.1 C67.2 C68.2 C69.2 C71.2 C73.2 C74.2 CIN1.2 CIN2.2 CIN3.2 CIN4.2 CIN5.2 CIN6.2 CIN7.2 CIN8.2 CIN9.2 CIN10.2 CIN11.2 CIN12.2 CIN13.2 COUT1.2 COUT2.2 COUT3.2 COUT3.3(GND) COUT4.2 COUT4.3(GND) COUT5.2 COUT5.3(GND) COUT6.2 COUT6.3(GND) COUT7.2 COUT7.3(GND) COUT8.2 COUT8.3(GND) COUT9.2 COUT10.2 COUT11.2 COUT12.2 COUT13.2 COUT13.3(GND) COUT14.2 COUT14.3(GND) COUT15.2 COUT15.3(GND) COUT16.2 COUT16.3(GND) COUT17.2 COUT17.3(GND) COUT18.2 COUT18.3(GND) COUT19.2 COUT20.2 COUT21.2 COUT21.3(GND) COUT22.2 COUT22.3(GND) COUT23.2 COUT23.3(GND) COUT24.2 COUT24.3(GND) COUT25.2 COUT25.3(GND) COUT26.2 COUT26.3(GND) COUT27.2 COUT27.3(GND) COUT28.2 COUT28.3(GND) D7.2 D9.2 D12.2 D21.2 E8.1 E10.1 E12.1 J4.1 J5.1 J6.1 J8.1 J9.2(GND2) J9.3(GND) J9.4(GND) J9.5(GND) J10.2(GND2) J10.3(GND) J10.4(GND) J10.5(GND) J11.7(SGND) J12.7(SGND) JP1.3 JP2.4 JP3.3 JP5.3 Q11.1 Q11.2 Q11.3 Q12.2(EMITTER) R6.1 R12.2 R13.1 R14.2 R22.2 R23.1 R26.2 R34.2 R39.2 R40.2 R42.1 R44.1 R49.2 R61.2 R62.1 R69.1 R71.2 R83.2 R84.2 R86.1 R88.1 R94.2 R104.2 R107.2 R108.1 R109.2 R113.1 R116.1 R117.2 R125.2 R126.2 R130.1 R131.2 R137.2 R138.2 R139.2 R140.1 R149.1 R152.1 R154.1 R162.1 R168.2 R169.2 R171.2 R172.2 R177.1 R187.2 R188.2 R189.2 R190.2 R191.2 RN1.1 U1.4(AGND) U1.12(PGND) U1.13(PGND) U1.14(PGND) U1.15(PGND) U1.28(PGND) U1.32(AGND) U1.34(PGND) U2.9(GND) U2.13(EP) U3.10(GND) U3.19(GND) U3.37(GND) U4.4(AGND) U4.12(PGND) U4.13(PGND) U4.14(PGND) U4.15(PGND) U4.28(PGND) U4.32(AGND) U4.34(PGND) U5.9(GND) U5.13(EP) U6.6(GND) U6.17(GND) U7.4(AGND) U7.12(PGND) U7.13(PGND) U7.14(PGND) U7.15(PGND) U7.28(PGND) U7.32(AGND) U7.34(PGND) U8.9(GND) U8.13(EP) U9.10(GND) U9.19(GND) U9.37(GND) U10.4(AGND) U10.12(PGND) U10.13(PGND) U10.14(PGND) U10.15(PGND) U10.28(PGND) U10.32(AGND) U10.34(PGND) U11.9(GND) U11.13(EP) U12.6(GND) U12.17(GND) U13.4(GND) U13.9(GND) U14.4(GND) U14.9(GND) U15.11(GND) U16.11(GND) U17.1(GND*) U17.2(GND) U18.2 U19.5(GND) U19.11(GND) U20.4(GND)
VIN: C52.1 C57.1 C71.1 CIN5.1 CIN6.1 CIN7.1 CIN10.1 CIN13.1 D9.1 E11.1 J7.1 R30.1 R37.1 R41.1 R45.1 R54.1 R55.1 R75.1 R82.1 R85.1 R91.1 R97.1 R98.1 R114.1 R115.1 R118.1 R119.1 R120.1 R121.1 R127.1 R128.1 R153.2 R170.1 R179.2 RS1.1 RS2.1 RS3.1 RS4.1 U6.1(VCC1) U6.12(VCC2) U12.1(VCC1) U12.12(VCC2) U15.8(IN1) U15.9(IN2) U16.8(IN1) U16.9(IN2) U19.4(VIN)
VIN1: C22.1 CIN1.1 CIN2.1 D1.2 Q3.1 Q3.2 Q3.3 R54.2 U1.8(VIN) U1.9(VIN) U1.10(VIN) U1.11(VIN) U1.33(VIN) U6.4(OUT1)
VIN2: C26.1 CIN3.1 CIN4.1 D2.2 Q4.1 Q4.2 Q4.3 R55.2 U4.8(VIN) U4.9(VIN) U4.10(VIN) U4.11(VIN) U4.33(VIN) U6.9(OUT2)
VIN3: C44.1 CIN8.1 CIN9.1 D3.2 Q7.1 Q7.2 Q7.3 R97.2 U7.8(VIN) U7.9(VIN) U7.10(VIN) U7.11(VIN) U7.33(VIN) U12.4(OUT1)
VIN4: C48.1 CIN11.1 CIN12.1 D4.2 Q8.1 Q8.2 Q8.3 R98.2 U10.8(VIN) U10.9(VIN) U10.10(VIN) U10.11(VIN) U10.33(VIN) U12.9(OUT2)
2R5VREF: C59.1 C60.1 R106.2 R111.2 R136.2 R147.2 U17.6(VOUT)
/FLT1: D14.1 R48.1 R118.2 U6.15(~{FAULT1})
/FLT2: D15.1 R50.1 R119.2 U6.14(~{FAULT2})
/FLT3: D16.1 R93.1 R120.2 U12.15(~{FAULT1})
/FLT4: D17.1 R95.1 R121.2 U12.14(~{FAULT2})
CLKINA: E4.1 J11.8(CLKIN) JP2.2 JP2.3 U3.32(MODE/PLLIN)
CLKOUTA: R68.1 TP17.1 U3.33(CLKOUT)
CLKOUTB: E6.1 J12.8(CLKOUT) U9.33(CLKOUT)
HIZB1: D14.2 R46.2 R48.2 R112.1 U3.23(HIZB1)
HIZB2: D15.2 R50.2 R52.1 R101.1 R164.1 R180.1 U3.6(HIZB2)
HIZB3: D16.2 R89.2 R93.2 R103.1 R165.1 R181.1 U9.23(HIZB1)
HIZB4: D17.2 R95.2 R96.1 R105.1 R166.1 R182.1 U9.6(HIZB2)
ILIM: J11.6(ILIM) J12.6(ILIM) R19.2 R22.1 U3.29(ILIM1) U3.36(ILIM2) U9.29(ILIM1) U9.36(ILIM2)
INTVCCA: C15.1 R1.1 R9.1 R17.1 R19.1 R25.2 R36.1 U3.34(INTVCC)
INTVCCB: C37.1 R60.1 R70.2 R80.1 U9.34(INTVCC)
ITEMP: R102.2 U3.1(ITEMP2) U3.28(ITEMP1) U9.1(ITEMP2) U9.28(ITEMP1)
ITH: C8.2 C32.2 C68.1 R16.2 R155.2 R156.1 U3.2(ITH2) U3.27(ITH1) U9.2(ITH2) U9.27(ITH1) U18.3
ITHFLTR: C51.1 R161.2 R163.1 R164.2 R165.2 R166.2
REV: JP5.2 R178.2 U2.7(REV) U5.7(REV) U8.7(REV) U11.7(REV)
RUN: J11.5(RUN) J12.5(RUN) Q12.3(COLLECTOR) R64.2 U3.9(RUN2) U3.20(RUN1) U9.9(RUN2) U9.20(RUN1) U20.1(OUT)
SNSDC1+: C12.1 R18.2 R188.1 U3.18(SNSDC1+)
SNSDC2+: C16.2 R29.1 R189.1 U3.11(SNSDC2+)
SNSDC3+: C34.1 R65.2 R190.1 U9.18(SNSDC1+)
SNSDC4+: C38.2 R72.1 R191.1 U9.11(SNSDC2+)
TK/SS: C9.1 J11.3(TRACK/SS) J12.3(TRACK/SS) R10.1 R14.1 U3.5(TK/SS2) U3.24(TK/SS1) U9.5(TK/SS2) U9.24(TK/SS1)
VOS+: C4.1 E3.1 R7.2 R24.2
VOS-: C7.2 E5.1 R11.2 R34.1 R159.2 R160.1 U3.3(VOSNS2-) U3.26(VOSNS1-) U9.3(VOSNS2-) U9.26(VOSNS1-)
VOSNS: C4.2 C7.1 R7.1 R11.1 R157.2 R158.1 U3.4(VOSNS2+) U3.25(VOSNS1+) U9.4(VOSNS2+) U9.25(VOSNS1+)
VOUT: C50.1 COUT3.1 COUT4.1 COUT5.1 COUT6.1 COUT7.1 COUT8.1 COUT13.1 COUT14.1 COUT15.1 COUT16.1 COUT17.1 COUT18.1 COUT21.1 COUT22.1 COUT23.1 COUT24.1 COUT25.1 COUT26.1 COUT27.1 COUT28.1 J1.1 J2.1 J3.1 J9.1 Q1.5 Q2.5 Q5.5 Q6.5 Q10.2(D) R24.1 R47.2 R51.2 R90.2 R92.2 R132.2 R145.2 R148.2 R187.1 U2.8(OUT) U5.8(OUT) U8.8(OUT) U11.8(OUT) U13.6(-IN_B)
VOUT1: C5.1 COUT1.1 COUT2.1 L1.2 Q1.1 Q1.2 Q1.3 R21.2 R47.1 U2.1(VIN) U2.12(SOURCE)
VOUT2: C21.1 COUT9.1 COUT10.1 L2.2 Q2.1 Q2.2 Q2.3 R28.1 R51.1 U5.1(VIN) U5.12(SOURCE)
VOUT3: C29.1 COUT11.1 COUT12.1 L3.2 Q5.1 Q5.2 Q5.3 R67.2 R90.1 U8.1(VIN) U8.12(SOURCE)
VOUT4: C42.1 COUT19.1 COUT20.1 L4.2 Q6.1 Q6.2 Q6.3 R74.1 R92.1 U11.1(VIN) U11.12(SOURCE)
N25810785: J10.1 Q10.3(S) R109.1
N25810799: E7.1 Q10.1(G) R104.1
N27582565: R102.1 R108.2 RN1.2
N29272883: C56.2 U15.1(BYP2)
N29272887: R123.2 R126.1 U15.2(ADJ2)
N29272987: C55.2 U15.5(BYP1)
N29273014: R122.2 R125.1 U15.4(ADJ1)
N29282458: C63.2 U16.1(BYP2)
N29282462: R134.2 R138.1 U16.2(ADJ2)
N29282558: C62.2 U16.5(BYP1)
N29282587: R133.2 R137.1 U16.4(ADJ1)
N29282599: R127.2 R130.2 U16.7(~{SHDN1})
N29282613: R128.2 R131.1 U16.3(~{SHDN2})
N29334652: R115.2 R117.1 U15.3(~{SHDN2})
N29338381: R114.2 R116.2 U15.7(~{SHDN1})
N30995008: D5.2 D6.2 D7.1 D8.2 R39.1
N30995010: L1.1 R18.1 R20.1 U1.16(SW) U1.17(SW) U1.18(SW) U1.19(SW) U1.20(SW) U1.21(SW) U1.22(SW) U1.23(SW) U1.24(SW) U1.25(SW) U1.26(SW)
N30995022: R9.2 TP1.1 U1.31(EN/FAULT#)
N30995097: C25.2 D8.1 U6.8(FTMR2)
N30995113: R36.2 TP6.1 U4.31(EN/FAULT#)
N30995115: E1.1 R1.2 U3.15(PGOOD1)
N30995192: C1.2 R3.1 R5.1 R8.1 U1.3(VCC)
N30995204: C13.2 R20.2 U3.16(SNSAC1+)
N30995210: TP4.1 U3.22(PWMEN1)
N30995238: R8.2 R12.1 U1.30(TMON)
N30995262: R15.1 U1.1(PWM)
N30995264: R4.1 U1.5(BOOT)
N30995266: C3.1 C31.1 D18.2 JP1.2 R2.2 R6.2 R64.1
N30995280: C10.2 R16.1
N30995358: C23.2 D6.1 U6.5(FTMR1)
N30995387: L2.1 R27.2 R29.2 U4.16(SW) U4.17(SW) U4.18(SW) U4.19(SW) U4.20(SW) U4.21(SW) U4.22(SW) U4.23(SW) U4.24(SW) U4.25(SW) U4.26(SW)
N30995403: C12.2 C13.1 R21.1 U3.17(SNS1-)
N30995405: C18.2 R32.1 R35.1 R38.1 U4.3(VCC)
N30995409: R38.2 R40.1 U4.30(TMON)
N30995411: R33.1 U4.5(BOOT)
N30995437: R35.2 U4.2(ZCD#)
N30995477: C19.1 R33.2
N30995494: C19.2 U4.7(PHASE)
N30995510: R31.2 U4.1(PWM)
N30995873: C5.2 U2.10(CPO)
N30995923: JP2.1 R17.2
N30995943: C14.1 R27.1 U3.13(SNSAC2+)
N30995945: R5.2 U1.2(ZCD#)
N30996112: R25.1 R26.1 U3.30(PHMODE)
N30996132: C2.1 R4.2
N30996154: R45.2 R49.1 U6.7(CLS)
N30996156: C14.2 C16.1 R28.2 U3.12(SNS2-)
N30996202: R15.2 U3.21(PWM1)
N30996226: TP2.1 U2.5(~{STATUS})
N30996286: C2.2 U1.7(PHASE)
N30996374: R13.2 U2.4(OV)
N30996525: R23.2 U3.31(FREQ)
N30996529: C17.2 R30.2 U3.35(VIN)
N30996617: E2.1 R10.2
N30996780: Q4.4 R53.1 U6.10(GATE2)
N30996782: Q4.5 Q4.6 Q4.7 Q4.8 RS2.2 U6.11(SENSE2)
N30996784: Q3.4 R43.1 U6.3(GATE1)
N30996844: Q3.5 Q3.6 Q3.7 Q3.8 RS1.2 U6.2(SENSE1)
N30996898: R41.2 R44.2 U6.13(ON2) U6.16(ON1)
N30997090: D5.1 R37.2
N30997170: TP5.1 U3.7(PWMEN2)
N30997304: R31.1 U3.8(PWM2)
N30997638: C21.2 U5.10(CPO)
N30997673: TP7.1 U5.5(~{STATUS})
N30997721: R184.1 U5.11(GATE)
N31002178: D10.2 D11.2 D12.1 D13.2 R83.1
N31002180: L3.1 R65.1 R66.1 U7.16(SW) U7.17(SW) U7.18(SW) U7.19(SW) U7.20(SW) U7.21(SW) U7.22(SW) U7.23(SW) U7.24(SW) U7.25(SW) U7.26(SW)
N31002192: R60.2 TP9.1 U7.31(EN/FAULT#)
N31002267: C46.2 D13.1 U12.8(FTMR2)
N31002283: R80.2 TP14.1 U10.31(EN/FAULT#)
N31002362: C27.2 R56.1 R58.1 R59.1 U7.3(VCC)
N31002374: C35.2 R66.2 U9.16(SNSAC1+)
N31002380: TP12.1 U9.22(PWMEN1)
N31002408: R59.2 R61.1 U7.30(TMON)
N31002432: R63.1 U7.1(PWM)
N31002434: R57.1 U7.5(BOOT)
N31002479: R68.2 U9.32(MODE/PLLIN)
N31002528: C47.2 D11.1 U12.5(FTMR1)
N31002557: L4.1 R72.2 R73.2 U10.16(SW) U10.17(SW) U10.18(SW) U10.19(SW) U10.20(SW) U10.21(SW) U10.22(SW) U10.23(SW) U10.24(SW) U10.25(SW) U10.26(SW)
N31002573: C34.2 C35.1 R67.1 U9.17(SNS1-)
N31002575: C41.2 R78.1 R79.1 R81.1 U10.3(VCC)
N31002579: R81.2 R84.1 U10.30(TMON)
N31002581: R77.1 U10.5(BOOT)
N31002607: R79.2 U10.2(ZCD#)
N31002647: C40.1 R77.2
N31002670: C40.2 U10.7(PHASE)
N31002680: R76.2 U10.1(PWM)
N31003043: C29.2 U8.10(CPO)
N31003113: C36.1 R73.1 U9.13(SNSAC2+)
N31003115: R58.2 U7.2(ZCD#)
N31003282: R70.1 R71.1 U9.30(PHMODE)
N31003302: C28.1 R57.2
N31003324: R91.2 R94.1 U12.7(CLS)
N31003326: C36.2 C38.1 R74.2 U9.12(SNS2-)
N31003372: R63.2 U9.21(PWM1)
N31003396: TP10.1 U8.5(~{STATUS})
N31003416: C28.2 U7.7(PHASE)
N31003695: R69.2 U9.31(FREQ)
N31003699: C39.2 R75.2 U9.35(VIN)
N31003950: Q8.4 R99.1 U12.10(GATE2)
N31003952: Q8.5 Q8.6 Q8.7 Q8.8 RS4.2 U12.11(SENSE2)
N31003954: Q7.4 R87.1 U12.3(GATE1)
N31004068: R85.2 R88.2 U12.13(ON2) U12.16(ON1)
N31004260: D10.1 R82.2
N31004340: TP13.1 U9.7(PWMEN2)
N31004474: R76.1 U9.8(PWM2)
N31004808: C42.2 U11.10(CPO)
N31004843: TP15.1 U11.5(~{STATUS})
N31004891: R186.1 U11.11(GATE)
N32417060: JP4.2 R101.2 R103.2 R105.2
N32590566: R136.1 R140.2 U14.2(-IN_A)
N32596917: R132.1 R135.2 U14.3(+IN_A)
N32739575: R147.1 R149.2 U14.6(-IN_B)
N32747239: R145.1 R146.2 U14.5(+IN_B)
N32749137: R146.1 R150.2 R151.2 U14.7(OUT_B)
N32862831: Q12.1(BASE) R151.1 R152.2
N32978155: Q11.5 R148.1
N33017831: D1.1 D2.1 D3.1 D4.1 D18.1 R2.1 R153.1 R154.2
N34249540: R42.2 U5.4(OV)
N34301097: R86.2 U11.4(OV)
N34320631: Q7.5 Q7.6 Q7.7 Q7.8 RS3.2 U12.2(SENSE1)
N34549875: R62.2 U8.4(OV)
N34697667: R135.1 R139.1 R178.1 U14.1(OUT_A)
N34762558: R106.1 R107.1 R110.2 U13.5(+IN_B)
N34763129: R100.2 R161.1 U13.3(+IN_A)
N34785869: R111.1 R113.2 U13.2(-IN_A)
N35119910: J11.1(ITH) R155.1
N35124030: J12.1(ITH) R156.2
N35135245: J11.2(VOSNS) R157.1
N35136422: J12.2(VOSNS) R158.2
N35150767: J11.4(VOS-) R159.1
N35151361: J12.4(VOS-) R160.2
N35176543: D20.2 R110.1 U13.7(OUT_B)
N35219908: D19.2 R100.1 U13.1(OUT_A)
N35224175: D19.1 D20.1 JP4.1 R162.2
N35323102: R167.2 R168.1 U18.4
N35325623: R163.2 R167.1 U18.1
N35344026: C72.1 L5.1 U19.6(SW)
N35344055: JP3.2 R169.1 R170.2 U19.3(EN/UVLO)
N35344089: C72.2 U19.7(BOOST)
N35344101: C70.2 R171.1 R173.2 U19.1(FB)
N35344111: R172.1 U19.10(RT)
N35344162: R174.1 U19.9(PG)
N35501442: D22.1 D23.1 D24.1 D25.1 R175.1 R176.1
N35610833: R176.2 R177.2 U20.3(+IN)
N35752735: C73.1 D21.1 R179.1 U20.2(VS)
N35857078: R180.2 U5.6(~{FAULT})
N35872333: R182.2 U11.6(~{FAULT})
N35876606: R181.2 U8.6(~{FAULT})
N35955506: Q2.4 R184.2
N35959254: Q1.4 R183.2
N35968779: R185.1 U8.11(GATE)
N35972827: Q5.4 R185.2
N35980002: Q6.4 R186.2
N36061147: Q11.4 R150.1
N36062880: C22.2 R43.2
N36062882: R112.2 U2.6(~{FAULT})
N36062883: R183.1 U2.11(GATE)
N36062884: C26.2 R53.2
N36090543: C48.2 R99.2
N36090544: C44.2 R87.2

Not connected (* = marked no-connect by the designer): JP1 1*; JP3 1*; JP4 3; U1 6(NC) 27(GL) 35(GL); U3 14(PGOOD2); U4 6(NC) 27(GL) 35(GL); U7 6(NC) 27(GL) 35(GL); U9 14(PGOOD2) 15(PGOOD1); U10 6(NC) 27(GL) 35(GL); U17 3(NC) 5(NC)

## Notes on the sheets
sheet 1
- -A
- -B
- IDEAL ORING DIODES
- -A
- MODE
- PS
- BM
- CCM
- FSW = 400kHz
- INPUT HOT SWAP CIRCUITS
- -A
- 10V - 14V
- HIGH EFFICIENCY
- -B
- HIGH EFFICIENCY
- -B
- *
- IOUT(MAX)
- -A
- N+1 MOSFET FAILURE PROTECTION
- 90A
- -B
- HIGH EFFICIENCY CONVERTER
- 120A
- NOTE: UNLESS OTHERWISE SPECIFIED
- -A: STUFFED ON -A  ASSEMBLY ONLY
  -B: STUFFED ON -B ASSEMBLY ONLY
- 1.  ALL RESISTORS ARE IN OHMS, 0603.
  2.  ALL CAPACITORS ARE  0603.
- 4 PHASE HIGH CURRENT STEP-DOWN
  CONVERTER WITH VERY LOW DCR INDUCTOR
- OPT, OPTIONAL: NOT STUFFED
sheet 2
- IDEAL ORING DIODES
- -A
- FSW = 400kHz
- INPUT HOT SWAP CIRCUITS
- -A
- HIGH EFFICIENCY
- -B
- HIGH EFFICIENCY
- -B
- 4 PHASE HIGH CURRENT STEP-DOWN
  CONVERTER WITH VERY LOW DCR INDUCTOR
sheet 3
- OPTIONAL PHASE SHEDDING CIRCUIT
- DYNAMIC LOAD CIRCUIT
- DRMOS BIAS SUPPLY FOR HIGH EFFICIENCY CONVERTER
- -B
- PHASE SHED
- PHASE 3 AND 4 ARE SHED
- LOAD STEP
  2mV / Amp
- ISHED = 20A
- IHYST = 15A
- -B
- ITH COMPARATOR
- VOUT COMPARATOR
- Note 1:
  The 5.5VBIAS voltages were increased from 5.0V to 5.5V to comply with the FDMF5820DC PCN.
   This PCN changed the maximum allowable PWM voltage stress from 6V to VCC+0.3V.
  For cases where the 5V bias needs to be 5.0V, use this setup:
  Tie the VIN pin of the LTC3774 to INTVCC and tie these two pins to the 5V bias with a 2.2 Ohm resistor.
   Place a 4.7uF cap from the combined VIN and INTVCC pins to ground.
- -A
- DRMOS BIAS SUPPLY FOR MOSFET FAILURE PROTECTION CIRCUIT
- -A
- -B
- OPTIONAL NTC COMPENSATION NETWORK
- OPTIONAL COMPONENTS
- 10K
- 10K
- 10K
- 10K
- 150uF
- 1N448HWT
- 1N448HWT
- 1N448HWT
- 1N448HWT
- OVER-VOLTAGE COMPARATOR
- -A
- -B
- CONNECT TO PARALLEL DC2111A
- RIGHT ANGLE
  SOCKET
- RIGHT ANGLE
  HEADER
- Note 2:
  Over-voltage comparator A permits the LTC3774 converter
  to sink current during a VOUT over-voltage event by placing the ideal diodes in the “REVERSE I ALLOWED” mode when VOUT exceeds 1.3V.
  To allow comparator A to work as intended, remove the jumper at JP5.
  Comparator B is a back-up OVP comparator intended for cases where the VOUT sense lines are shorted together or
   VOUT is shorted to an external source and the ideal diodes are in the “DIODE” mode.
  When VOUT exceeds 1.5V, comparator B pulls down the RUN pin and turns on a MOSFET to discharge VOUT.
   VOUT and the RUN pin are released once VOUT falls below 0.4V.
- ALLOWED
- 4 PHASE HIGH CURRENT STEP-DOWN
  CONVERTER WITH VERY LOW DCR INDUCTOR
